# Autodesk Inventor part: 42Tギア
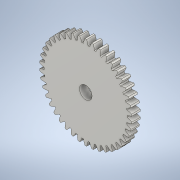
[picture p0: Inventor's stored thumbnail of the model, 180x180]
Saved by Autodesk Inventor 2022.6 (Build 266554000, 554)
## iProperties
CustomPartVersion: 1
Created: 2024-11
Part Number: 42Tギア
Material: Steel
Document SubType Name: Modeling
Designer: neo09
Categories: <?xml version="1.0" encoding="UTF-16"?> <MemberInstance><Categories><FamilyTemplate><FamilyTemplateParameter ValueType="xs:double" Id="1" ObjectReferenceKey="da
Density: 1 g/cm^3
Appearance: Steel
Author: neo09
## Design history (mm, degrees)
sketch "Sketch1"
  geometry: C1 r 11 at (0, 0)
  constraints: 1 centre point
  dimensions: "d0" = 22 diameter of C1 (= da_da)
extrude "Extrusion1" new body sketch "Sketch1" distance "d1" = 2 (= da_b); taper "d2" = 0 deg
workplane "Work Plane2"
sketch "Sketch2"
  geometry: C1 r 11 at (0, 0) reference; C2 r 10.5 at (0, 0)
  constraints: 1 centre point, 1 coincident
  dimensions: "d3" = 21 diameter of C2 (= da_d)
feature "ピッチ円直径" sketch "Sketch2" dims "d4" = 10, "d5" = 0
workplane "Work Plane8"
workplane "Work Plane9"
feature "平歯車" dims "d4" = 10, "da_b" = 2, "da_d" = 21, "da_aw" = 24.75, "da_da" = 22, "da_df" = 19.75, "da_dw" = 21, angle "da_beta" = 0 deg, "da_lefttooth" = 0, "da_righttooth" = 0
sketch "スケッチ3"
  geometry: C1 r 1.5 at (0, 0); 1 further point
  constraints: 1 centre point, 1 coincident
  dimensions: "d49" = 3 diameter of C1
extrude "押し出し2" cut sketch "スケッチ3" distance "d50" = 10; taper "d51" = 0 deg
body "Solid1"
body "Srf1"
other parameters: "d16" = 24.75 (= da_aw), "d17" = 0, "d34" = 0.748 (computed from da_z), "d39" = 0, "d41" = 0, "d43" = 24.75 (= da_aw), "d46" = 24.75 (= da_aw), "d47" = 0, "d48" = 0
